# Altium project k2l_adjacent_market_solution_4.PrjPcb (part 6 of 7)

## Sheet system_power_01.SchDoc
size 431 x 279 mm; Date: Not shown in title block; ApprovedBy: Not shown in title block; CheckedBy: Not shown in title block; Author: Not shown in title block; CompanyName: Not shown in title block; DrawnBy: a0271760; Engineer: Not shown in title block; Organization: Not shown in title block; Address1: Not shown in title block; Address2: Not shown in title block; Address3: Not shown in title block; Address4: Not shown in title block; DocumentNumber: 34; Revision: Use project parameter SCH_Rev; SheetNumber: 34; SheetTotal: 38; PageSetup: Record=PageOptions¦CenterHorizontal=True¦CenterVertical=True¦PrintScale=0.64¦XCorrection=1.00¦YCorrection=1.00¦PrintKind=0¦BorderSize=5000000¦LeftOffset=0¦BottomOffset=0¦Orientation=2¦PaperLength=1000¦PaperWidth=1000¦Scale=100¦PaperSource=15¦PrintQuality=-3¦MediaType=1¦DitherType=10¦PrintScaleMode=1¦PaperKind=Letter¦PaperIndex=1
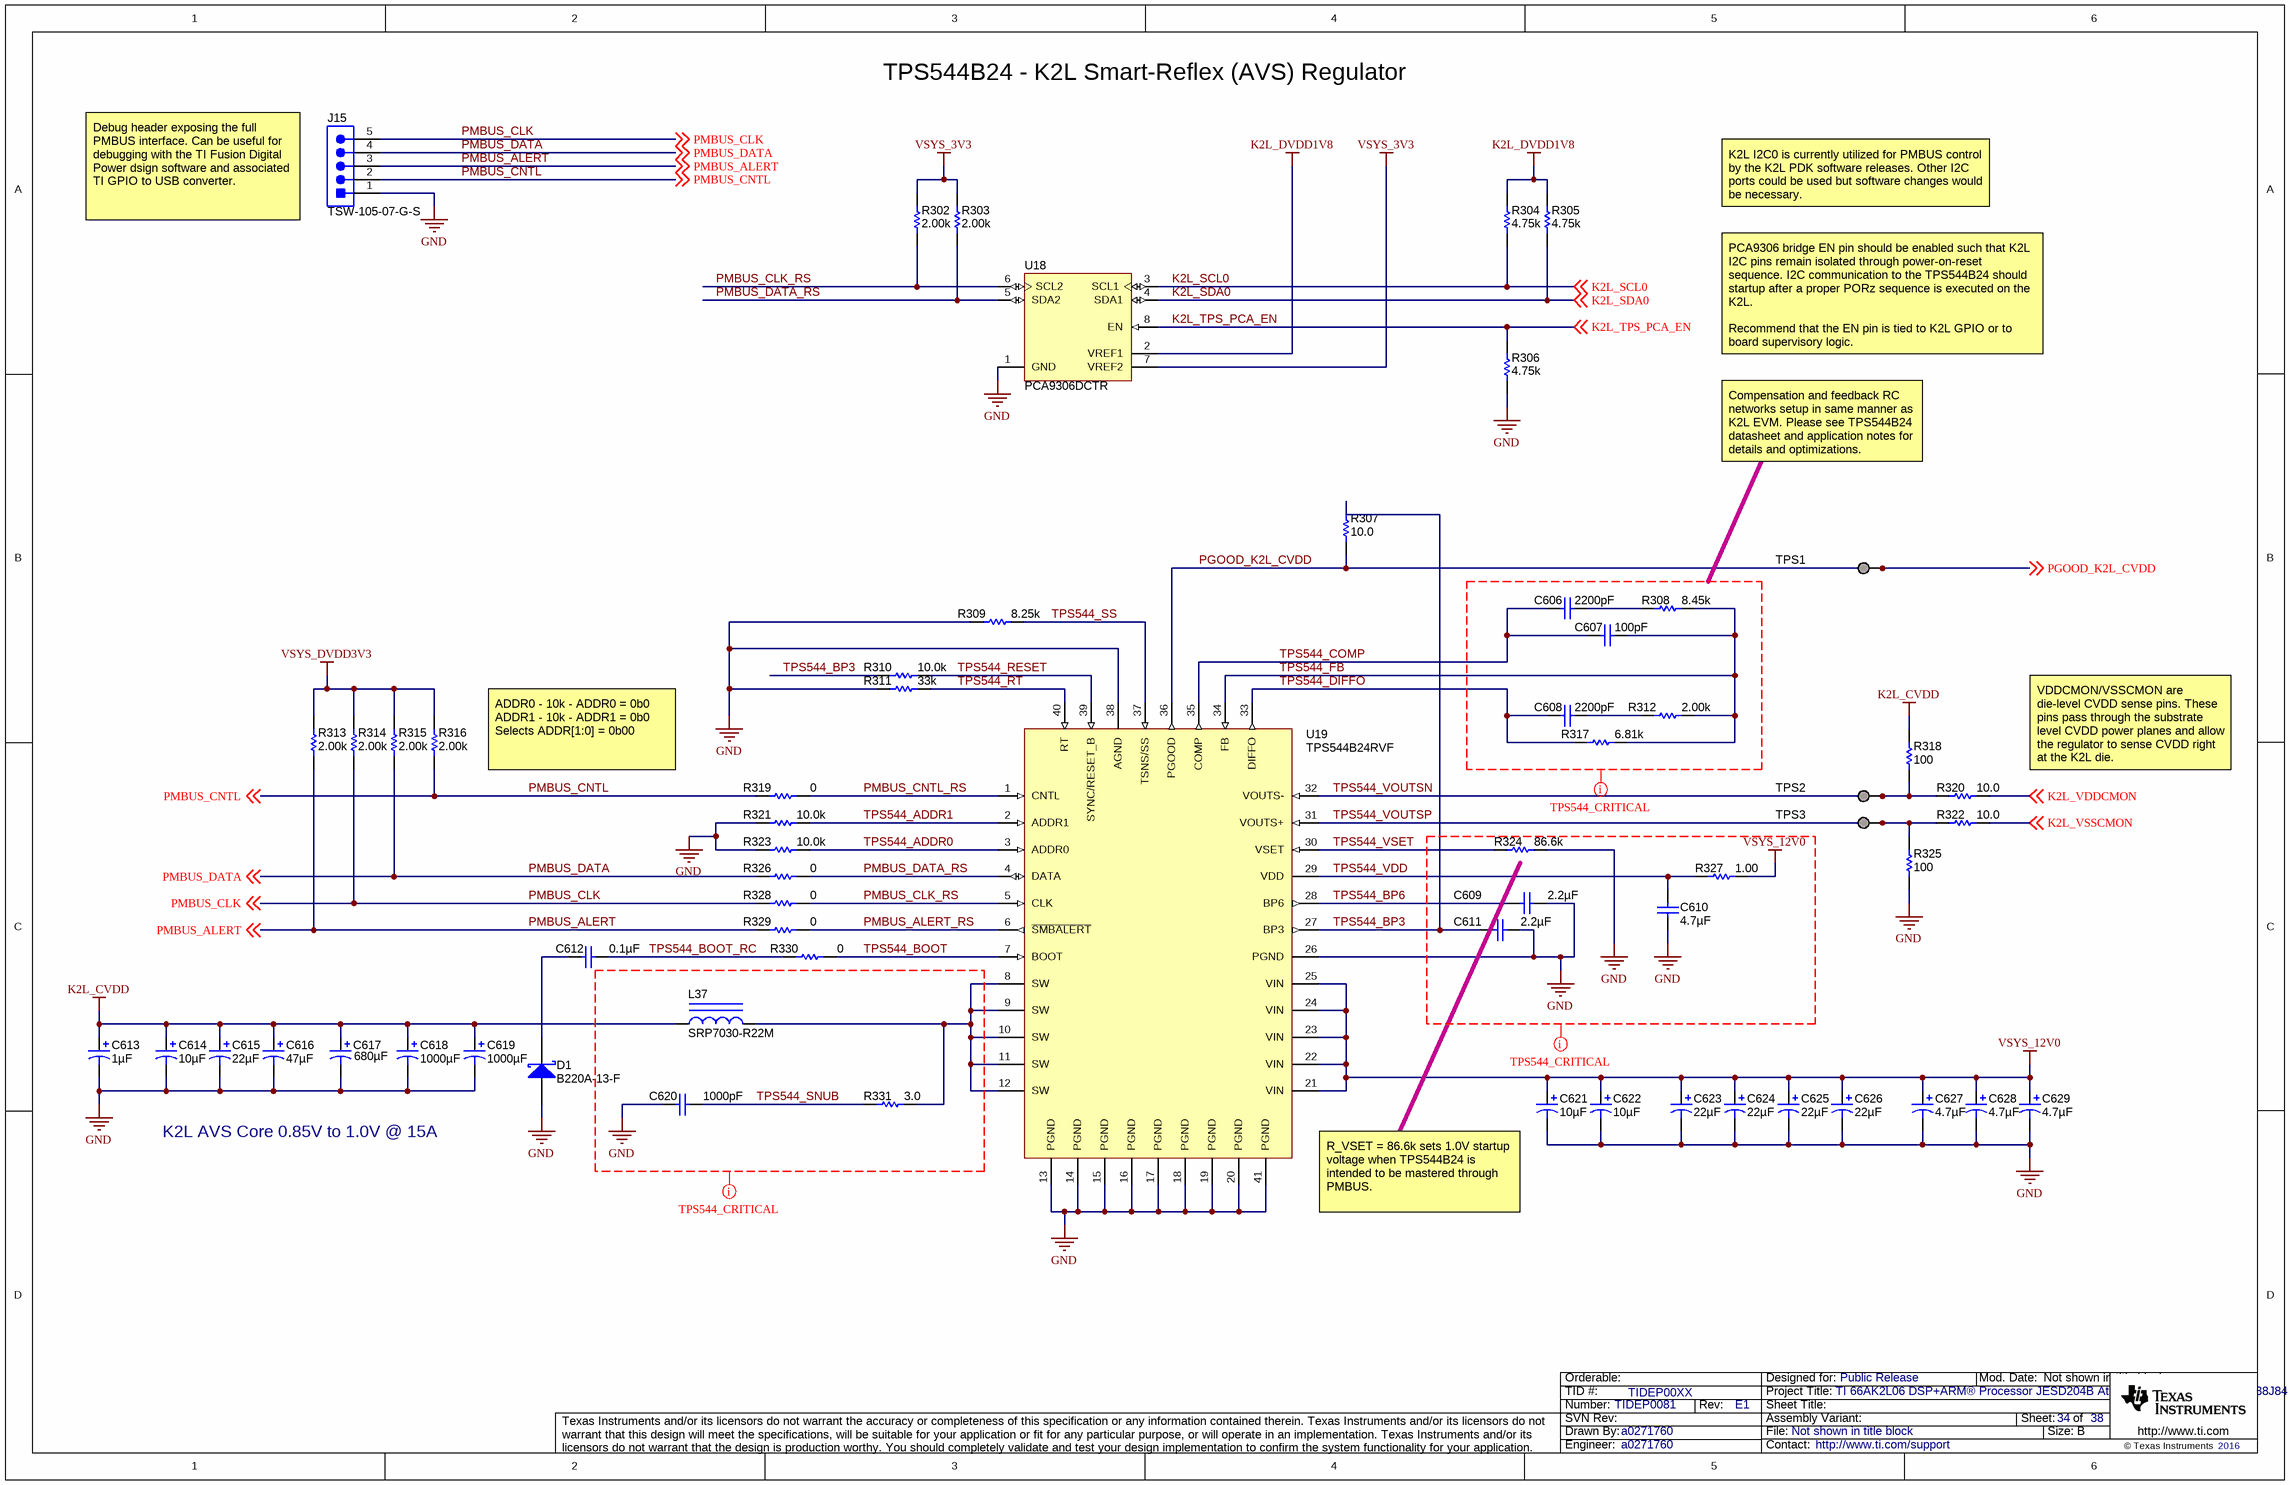
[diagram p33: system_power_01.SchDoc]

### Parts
C606  ValueDisplayed: 2200pF  [0402]  (hidden comment: C1005X7R1H222M)
C607  ValueDisplayed: 100pF  [0402]  (hidden comment: GRM1555C1H101JA01D)
C608  ValueDisplayed: 2200pF  [0402]  (hidden comment: C1005X7R1H222M)
C609  ValueDisplayed: 2.2µF  [0402]  (hidden comment: GRM155B31A225ME95)
C610  ValueDisplayed: 4.7µF  [0402]  (hidden comment: GRM155R61E475ME15)
C611  ValueDisplayed: 2.2µF  [0402]  (hidden comment: GRM155B31A225ME95)
C612  ValueDisplayed: 0.1µF  [0402]  (hidden comment: GCM155R7IC104KA55D)
C613  ValueDisplayed: 1µF  [3216-18]  (hidden comment: T495A105K020ZTE3K0)
C614  ValueDisplayed: 10µF  [3216-18]  (hidden comment: T495A106K010ATE1K8)
C615  ValueDisplayed: 22µF  [3216-18]  (hidden comment: T495A226M010ZTE1K2ZV17)
C616  ValueDisplayed: 47µF  [6032-28]  (hidden comment: T495C476K006ATE250)
C617  ValueDisplayed: 680µF  [7343-31]  (hidden comment: TPSD687K004R0045)
C618  ValueDisplayed: 1000µF  [7260-38]  (hidden comment: T495E108K004ATE050)
C619  ValueDisplayed: 1000µF  [7260-38]  (hidden comment: T495E108K004ATE050)
C620  ValueDisplayed: 1000pF  [0402]  (hidden comment: GRM155R60J102KA01D)
C621  ValueDisplayed: 10µF  [3216-18]  (hidden comment: T495A106K010ATE1K8)
C622  ValueDisplayed: 10µF  [3216-18]  (hidden comment: T495A106K010ATE1K8)
C623  ValueDisplayed: 22µF  [3216-18]  (hidden comment: T495A226M010ZTE1K2ZV17)
C624  ValueDisplayed: 22µF  [3216-18]  (hidden comment: T495A226M010ZTE1K2ZV17)
C625  ValueDisplayed: 22µF  [3216-18]  (hidden comment: T495A226M010ZTE1K2ZV17)
C626  ValueDisplayed: 22µF  [3216-18]  (hidden comment: T495A226M010ZTE1K2ZV17)
C627  ValueDisplayed: 4.7µF  [3216-18]  (hidden comment: T495A475K010ZTE1K4)
C628  ValueDisplayed: 4.7µF  [3216-18]  (hidden comment: T495A475K010ZTE1K4)
C629  ValueDisplayed: 4.7µF  [3216-18]  (hidden comment: T495A475K010ZTE1K4)
D1  B220A-13-F  [SMA]
J15  TSW-105-07-G-S  [TSW-105-07-G-S]
L37  SRP7030-R22M  [SRP7030]
R302  ValueDisplayed: 2.00k  [0402]  (hidden comment: CRCW04022K00FKED)
R303  ValueDisplayed: 2.00k  [0402]  (hidden comment: CRCW04022K00FKED)
R304  ValueDisplayed: 4.75k  [0402]  (hidden comment: CRCW04024K75FKED)
R305  ValueDisplayed: 4.75k  [0402]  (hidden comment: CRCW04024K75FKED)
R306  ValueDisplayed: 4.75k  [0402]  (hidden comment: CRCW04024K75FKED)
R307  ValueDisplayed: 10.0  [0402]  (hidden comment: CRCW040210R0FKED)
R308  ValueDisplayed: 8.45k  [0402]  (hidden comment: CRCW04028K45FKED)
R309  ValueDisplayed: 8.25k  [0402]  (hidden comment: CRCW04028K25FKED)
R310  ValueDisplayed: 10.0k  [0402]  (hidden comment: CRCW040210K0FKED)
R311  ValueDisplayed: 33k  [0402]  (hidden comment: CRCW040233K0JNED)
R312  ValueDisplayed: 2.00k  [0402]  (hidden comment: CRCW04022K00FKED)
R313  ValueDisplayed: 2.00k  [0402]  (hidden comment: CRCW04022K00FKED)
R314  ValueDisplayed: 2.00k  [0402]  (hidden comment: CRCW04022K00FKED)
R315  ValueDisplayed: 2.00k  [0402]  (hidden comment: CRCW04022K00FKED)
R316  ValueDisplayed: 2.00k  [0402]  (hidden comment: CRCW04022K00FKED)
R317  ValueDisplayed: 6.81k  [0402]  (hidden comment: CRCW04026K81FKED)
R318  ValueDisplayed: 100  [0402]  (hidden comment: ERJ-2RKF1000X)
R319  ValueDisplayed: 0  [0402]  (hidden comment: CRCW04020000Z0ED)
R320  ValueDisplayed: 10.0  [0402]  (hidden comment: CRCW040210R0FKED)
R321  ValueDisplayed: 10.0k  [0402]  (hidden comment: CRCW040210K0FKED)
R322  ValueDisplayed: 10.0  [0402]  (hidden comment: CRCW040210R0FKED)
R323  ValueDisplayed: 10.0k  [0402]  (hidden comment: CRCW040210K0FKED)
R324  ValueDisplayed: 86.6k  [0402]  (hidden comment: CRCW040286K6FKED)
R325  ValueDisplayed: 100  [0402]  (hidden comment: ERJ-2RKF1000X)
R326  ValueDisplayed: 0  [0402]  (hidden comment: CRCW04020000Z0ED)
R327  ValueDisplayed: 1.00  [1206]  (hidden comment: ERJ-8RQF1R0V)
R328  ValueDisplayed: 0  [0402]  (hidden comment: CRCW04020000Z0ED)
R329  ValueDisplayed: 0  [0402]  (hidden comment: CRCW04020000Z0ED)
R330  ValueDisplayed: 0  [0402]  (hidden comment: CRCW04020000Z0ED)
R331  ValueDisplayed: 3.0  [0402]  (hidden comment: CRCW04023R00JNED)
TPS1  TESTPOINT  [TESTPOINT]  (value not drawn)  (no BOM)
TPS2  TESTPOINT  [TESTPOINT]  (value not drawn)  (no BOM)
TPS3  TESTPOINT  [TESTPOINT]  (value not drawn)  (no BOM)
U18  PCA9306DCTR  [DCT0008A_N]
U19  TPS544B24RVF  [RVF0040A]

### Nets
GND: C609.1 C610.2 C611.1 C613.2(-) C614.2(-) C615.2(-) C616.2(-) C617.2(-) C618.2(-) C619.2(-) C620.2 C621.2(-) C622.2(-) C623.2(-) C624.2(-) C625.2(-) C626.2(-) C627.2(-) C628.2(-) C629.2(-) D1.2(A) J15.1 R306.1 R309.1 R311.2 R321.1 R323.1 R324.2 R325.1 U18.1(GND) U19.13(PGND) U19.14(PGND) U19.15(PGND) U19.16(PGND) U19.17(PGND) U19.18(PGND) U19.19(PGND) U19.20(PGND) U19.26(PGND) U19.38(AGND) U19.41(PGND)  [project net DAC_OUT0N_T1]
K2L_CVDD: C613.1(+) C614.1(+) C615.1(+) C616.1(+) C617.1(+) C618.1(+) C619.1(+) L37.1 R318.2
K2L_DVDD1V8: R304.2 R305.2 U18.2(VREF1)
VSYS_3V3: R302.2 R303.2 U18.7(VREF2)
VSYS_12V0: C621.1(+) C622.1(+) C623.1(+) C624.1(+) C625.1(+) C626.1(+) C627.1(+) C628.1(+) C629.1(+) R327.2 U19.21(VIN) U19.22(VIN) U19.23(VIN) U19.24(VIN) U19.25(VIN)
VSYS_DVDD3V3: R313.2 R314.2 R315.2 R316.2
K2L_SCL0: R304.1 U18.3(SCL1) ; off-sheet K2L_SCL0
K2L_SDA0: R305.1 U18.4(SDA1) ; off-sheet K2L_SDA0
K2L_TPS_PCA_EN: R306.2 U18.8(EN) ; off-sheet K2L_TPS_PCA_EN
K2L_VDDCMON: R320.2 ; off-sheet K2L_VDDCMON
K2L_VSSCMON: R322.2 ; off-sheet K2L_VSSCMON
PGOOD_K2L_CVDD: R307.2 TPS1.1 U19.36(PGOOD) ; off-sheet PGOOD_K2L_CVDD
PMBUS_ALERT: J15.3 R313.1 R329.1 ; off-sheet PMBUS_ALERT
PMBUS_ALERT_RS: R329.2 U19.6(~{SMBALERT})
PMBUS_CLK: J15.5 R314.1 R328.1 ; off-sheet PMBUS_CLK
PMBUS_CLK_RS: R302.1 R328.2 U18.6(SCL2) U19.5(CLK)
PMBUS_CNTL: J15.2 R316.1 R319.1 ; off-sheet PMBUS_CNTL
PMBUS_CNTL_RS: R319.2 U19.1(CNTL)
PMBUS_DATA: J15.4 R315.1 R326.1 ; off-sheet PMBUS_DATA
PMBUS_DATA_RS: R303.1 R326.2 U18.5(SDA2) U19.4(DATA)
TPS544_ADDR0: R323.2 U19.3(ADDR0)
TPS544_ADDR1: R321.2 U19.2(ADDR1)
TPS544_BOOT: R330.2 U19.7(BOOT)
TPS544_BOOT_RC: C612.1 R330.1
TPS544_BP3: C611.2 R307.1 R310.1 U19.27(BP3)
TPS544_BP6: C609.2 U19.28(BP6)
TPS544_COMP: C606.2 C607.1 U19.35(COMP)
TPS544_DIFFO: C608.2 R317.1 U19.33(DIFFO)
TPS544_FB: C607.2 R308.2 R312.2 R317.2 U19.34(FB)
TPS544_RESET: R310.2 U19.39(SYNC/RESET_B)
TPS544_RT: R311.1 U19.40(RT)
TPS544_SNUB: C620.1 R331.1
TPS544_SS: R309.2 U19.37(TSNS/SS)
TPS544_VDD: C610.1 R327.1 U19.29(VDD)
TPS544_VOUTSN: R318.1 R320.1 TPS2.1 U19.32(VOUTS-)
TPS544_VOUTSP: R322.1 R325.2 TPS3.1 U19.31(VOUTS+)
TPS544_VSET: R324.1 U19.30(VSET)
NetC606_1: C606.1 R308.1
NetC608_1: C608.1 R312.1
NetC612_2: C612.2 D1.1(K)
NetL37_2: L37.2 R331.2 U19.8(SW) U19.9(SW) U19.10(SW) U19.11(SW) U19.12(SW)

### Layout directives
net class Undefined: (no net found under the mark), GND, TPS544_SNUB, VSYS_12V0

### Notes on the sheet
- TPS544B24 - K2L Smart-Reflex (AVS) Regulator
- Debug header exposing the full PMBUS interface. Can be useful for debugging with the TI Fusion Digital Power dsign software and associated TI GPIO to USB converter.
- K2L I2C0 is currently utilized for PMBUS control by the K2L PDK software releases. Other I2C ports could be used but software changes would be necessary.
- PCA9306 bridge EN pin should be enabled such that K2L I2C pins remain isolated through power-on-reset sequence. I2C communication to the TPS544B24 should startup after a proper PORz sequence is executed on the K2L.
  Recommend that the EN pin is tied to K2L GPIO or to board supervisory logic.
- Compensation and feedback RC networks setup in same manner as K2L EVM. Please see TPS544B24 datasheet and application notes for details and optimizations.
- ADDR0 - 10k - ADDR0 = 0b0
  ADDR1 - 10k - ADDR1 = 0b0
  Selects ADDR[1:0] = 0b00
- VDDCMON/VSSCMON are die-level CVDD sense pins. These pins pass through the substrate level CVDD power planes and allow the regulator to sense CVDD right at the K2L die.
- K2L AVS Core 0.85V to 1.0V @ 15A
- R_VSET = 86.6k sets 1.0V startup voltage when TPS544B24 is intended to be mastered through PMBUS.

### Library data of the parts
C606 C608 = C1005X7R1H222M: CAP, CERM, 2200 pF, 50 V, +/- 20%, X7R, 0402; Manufacturer: TDK; Polarized: N; CompType: Capacitor; Value: 2200pF; U/M: EA; Cap_F: 0.0000000022; Tolerance_%: 20; ESR_ohm: 0.005; Value1: 0.005 ohm; VDC_V: 50; Value2: 50V; TaMin_C: -55; TaMax_C: 125
C607 = GRM1555C1H101JA01D: CAP, CERM, 100 pF, 50 V, +/- 5%, C0G/NP0, 0402; Manufacturer: MuRata; Polarized: N; CompType: Capacitor; Value: 100pF; U/M: EA; Cap_F: 0.0000000001; Tolerance_%: 5; Value1: Unknown; VDC_V: 50; Value2: 50V; TaMin_C: -55; TaMax_C: 125
C609 C611 = GRM155B31A225ME95: CAP, CERM, 2.2 µF, 10 V, +/- 20%, B, 0402; Manufacturer: MuRata; Polarized: N; CompType: Capacitor; Value: 2.2uF; U/M: EA; Cap_F: 0.0000022; Tolerance_%: 20; Value1: Unknown; VDC_V: 10; Value2: 10V; TaMin_C: -25; TaMax_C: 85
C610 = GRM155R61E475ME15: CAP, CERM, 4.7 µF, 25 V, +/- 20%, X5R, 0402; Manufacturer: MuRata; Polarized: N; CompType: Capacitor; Value: 4.7uF; U/M: EA; Cap_F: 0.0000047; Tolerance_%: 20; Value1: Unknown; VDC_V: 25; Value2: 25V; TaMin_C: -55; TaMax_C: 85
C612 = GCM155R7IC104KA55D: CAP, CERM, 0.1 µF, 16 V, +/- 10%, X7R, 0402; Manufacturer: MuRata; Polarized: N; CompType: Capacitor; Value: 0.1uF; U/M: EA; Cap_F: 0.0000001; Tolerance_%: 10; Value1: Unknown; VDC_V: 16; Value2: 16V; TaMin_C: -55; TaMax_C: 125
C613 = T495A105K020ZTE3K0: CAP, TA, 1 µF, 20 V, +/- 10%, 3 ohm, SMD; Manufacturer: Kemet; Polarized: Y; CompType: Capacitor; Value: 1uF; U/M: EA; Cap_F: 0.000001; Tolerance_%: 10; Value1: 3 ohm; VDC_V: 20; Value2: 20V; ESR_ohm: 3; IRMS_A: 0.142; TaMin_C: -55; TaMax_C: 125; Cap_Case: A
C614 C621 C622 = T495A106K010ATE1K8: CAP, TA, 10 µF, 10 V, +/- 10%, 1.8 ohm, SMD; Manufacturer: Kemet; Polarized: Y; CompType: Capacitor; Value: 10uF; U/M: EA; Cap_F: 0.00001; Tolerance_%: 10; Value1: 1.8 ohm; Value2: 10V; ESR_ohm: 1.8; TaMin_C: -55; TaMax_C: 125; Cap_Case: A
C615 C623-C626 = T495A226M010ZTE1K2ZV17: CAP, TA, 22 µF, 10 V, +/- 20%, 1.2 ohm, SMD; Manufacturer: Kemet; Polarized: Y; CompType: Capacitor; Value: 22uF; U/M: EA; Cap_F: 0.000022; Tolerance_%: 20; Value1: 1.2 ohm; VDC_V: 10; Value2: 10V; ESR_ohm: 1.2; TaMin_C: -55; TaMax_C: 125; Cap_Case: A
C616 = T495C476K006ATE250: CAP, TA, 47 µF, 6.3 V, +/- 10%, 0.25 ohm, SMD; Manufacturer: Kemet; Polarized: Y; CompType: Capacitor; Value: 47uF; U/M: EA; Cap_F: 0.000047; Tolerance_%: 10; VDC_V: 6.3; Value2: 6.3V; ESR_ohm: 0.25; IRMS_A: 0.597; TaMin_C: -55; TaMax_C: 125; Cap_Case: C
C617 = TPSD687K004R0045: CAP, TA, 680 µF, 4 V, +/- 10%, 0.045 ohm, SMD; Manufacturer: AVX; Polarized: Y; CompType: Capacitor; Value: 680uF; U/M: EA; Cap_F: 0.00068; Tolerance_%: 10; VDC_V: 4; Value2: 4V; ESR_ohm: 0.045; IRMS_A: 1.643; TaMin_C: -55; TaMax_C: 125; Cap_Case: D
C618 C619 = T495E108K004ATE050: CAP, TA, 1000 µF, 4 V, +/- 10%, 0.05 ohm, SMD; Manufacturer: Kemet; Polarized: Y; CompType: Capacitor; Value: 1000uF; U/M: EA; Cap_F: 0.001; Tolerance_%: 10; VDC_V: 4; Value2: 4V; ESR_ohm: 0.05; IRMS_A: 1.8; TaMin_C: -55; TaMax_C: 125; Cap_Case: E
C620 = GRM155R60J102KA01D: CAP, CERM, 1000 pF, 6.3 V, +/- 10%, X5R, 0402; Manufacturer: MuRata; Polarized: N; CompType: Capacitor; Value: 1000pF; U/M: EA; Cap_F: 0.000000001; Tolerance_%: 10; Value1: Unknown; VDC_V: 6.3; Value2: 6.3V; TaMin_C: -55; TaMax_C: 85
C627-C629 = T495A475K010ZTE1K4: CAP, TA, 4.7 µF, 10 V, +/- 10%, 1.4 ohm, SMD; Manufacturer: Kemet; Polarized: Y; CompType: Capacitor; Value: 4.7uF; U/M: EA; Cap_F: 0.0000047; Tolerance_%: 10; Value1: 1.4 ohm; Value2: 10V; ESR_ohm: 1.4; IRMS_A: 0.216; TaMin_C: -55; TaMax_C: 125; Cap_Case: A
D1 = B220A-13-F: Diode, Schottky, 20 V, 2 A, SMA; Manufacturer: Diodes Inc.; U/M: EA; Vf_V: 0.5; Value: 20V; Value1: 2A; Value2: 0.5V; Io_A: 2; Vr_V: 20; TJmax_C: 150
J15 = TSW-105-07-G-S: Header, 100mil, 5x1, Gold, TH; Manufacturer: Samtec; SymbolCreator: a0412235; U/M: EA
L37 = SRP7030-R22M: Inductor, Shielded, Powdered Iron, 220 nH, 23 A, 0.0028 ohm, SMD; Manufacturer: Bourns; Value: 220nH; Ind_H: 220.0E-9; Imax_A: 23; Irms: 23A @ 40C rise; Isat: 36A @ 20% inductance drop; DCR_ohm: 0.0028; Value2: 23A
R302 R303 R312-R316 = CRCW04022K00FKED: RES, 2.00 k, 1%, 0.063 W, 0402; Manufacturer: Vishay-Dale; CompType: Resistor; Value: 2.00k; Res_ohm: 2000; Value_Code: 2k00; Tolerance_%: 1; Power_W: 0.063; Value2: 0.063W; VDC_V: 50; TempCo: 100 ppm/C; EIA_Code: E96; U/M: EA
R304-R306 = CRCW04024K75FKED: RES, 4.75 k, 1%, 0.063 W, 0402; Manufacturer: Vishay-Dale; CompType: Resistor; Value: 4.75k; Res_ohm: 4750; Value_Code: 4k75; Tolerance_%: 1; Power_W: 0.063; Value2: 0.063W; VDC_V: 50; TempCo: 100 ppm/C; EIA_Code: E96; U/M: EA
R307 R320 R322 = CRCW040210R0FKED: RES, 10.0, 1%, 0.063 W, 0402; Manufacturer: Vishay-Dale; CompType: Resistor; Value: 10.0; Res_ohm: 10; Value_Code: 10R0; Tolerance_%: 1; Power_W: 0.063; Value2: 0.063W; VDC_V: 50; TempCo: 100 ppm/C; EIA_Code: E96; U/M: EA
R308 = CRCW04028K45FKED: RES, 8.45 k, 1%, 0.063 W, 0402; Manufacturer: Vishay-Dale; CompType: Resistor; Value: 8.45k; Res_ohm: 8450; Value_Code: 8k45; Tolerance_%: 1; Power_W: 0.063; Value2: 0.063W; VDC_V: 50; TempCo: 100 ppm/C; EIA_Code: E96; U/M: EA
R309 = CRCW04028K25FKED: RES, 8.25 k, 1%, 0.063 W, 0402; Manufacturer: Vishay-Dale; CompType: Resistor; Value: 8.25k; Res_ohm: 8250; Value_Code: 8k25; Tolerance_%: 1; Power_W: 0.063; Value2: 0.063W; VDC_V: 50; TempCo: 100 ppm/C; EIA_Code: E96; U/M: EA
R310 R321 R323 = CRCW040210K0FKED: RES, 10.0 k, 1%, 0.063 W, 0402; Manufacturer: Vishay-Dale; CompType: Resistor; Value: 10.0k; Res_ohm: 10000; Value_Code: 10k0; Tolerance_%: 1; Power_W: 0.063; Value2: 0.063W; VDC_V: 50; TempCo: 100 ppm/C; EIA_Code: E96; U/M: EA
R311 = CRCW040233K0JNED: RES, 33 k, 5%, 0.063 W, 0402; Manufacturer: Vishay-Dale; CompType: Resistor; Value: 33k; Res_ohm: 33000; Value_Code: 33k0; Tolerance_%: 5; Power_W: 0.063; Value2: 0.063W; VDC_V: 50; TempCo: 200 ppm/C; EIA_Code: E24; U/M: EA
R317 = CRCW04026K81FKED: RES, 6.81 k, 1%, 0.063 W, 0402; Manufacturer: Vishay-Dale; CompType: Resistor; Value: 6.81k; Res_ohm: 6810; Value_Code: 6k81; Tolerance_%: 1; Power_W: 0.063; Value2: 0.063W; VDC_V: 50; TempCo: 100 ppm/C; EIA_Code: E96; U/M: EA
R318 R325 = ERJ-2RKF1000X: RES, 100, 1%, 0.1 W, 0402; Manufacturer: Panasonic; CompType: Resistor; Value: 100; Value_Code: 100R; Tolerance_%: 1; Power_W: 0.1; Value2: 0.1W; VDC_V: 50; TempCo: 100 ppm/C; EIA_Code: E96; U/M: EA
R319 R326 R328-R330 = CRCW04020000Z0ED: RES, 0, 5%, 0.063 W, 0402; Manufacturer: Vishay-Dale; CompType: Resistor; Value: 0; Value_Code: 0000; Tolerance_%: 5; Power_W: 0.063; Value2: 0.063W; VDC_V: 50; TempCo: 200 ppm/C; EIA_Code: E24; U/M: EA
R324 = CRCW040286K6FKED: RES, 86.6 k, 1%, 0.063 W, 0402; Manufacturer: Vishay-Dale; CompType: Resistor; Value: 86.6k; Res_ohm: 86600; Value_Code: 86k6; Tolerance_%: 1; Power_W: 0.063; Value2: 0.063W; VDC_V: 50; TempCo: 100 ppm/C; EIA_Code: E96; U/M: EA
R327 = ERJ-8RQF1R0V: RES, 1.00, 1%, 0.25 W, 1206; Manufacturer: Panasonic; CompType: Resistor; Value: 1.00; Res_ohm: 1; Value_Code: 1R00; Power_W: 0.25; Value2: 0.25W; TempCo: 200 ppm/C; EIA_Code: E96; U/M: EA
R331 = CRCW04023R00JNED: RES, 3.0, 5%, 0.063 W, 0402; Manufacturer: Vishay-Dale; CompType: Resistor; Value: 3.0; Res_ohm: 3; Value_Code: 3R00; Tolerance_%: 5; Power_W: 0.063; Value2: 0.063W; VDC_V: 50; TempCo: 200 ppm/C; EIA_Code: E24; U/M: EA
TPS1-TPS3 = TESTPOINT: TEST POINT.  No entry in BOM.
U18 = PCA9306DCTR: Dual Bi-Directional I2C-Bus and SMBus Voltage Level-Translator, 0 to 5.5 V, -40 to 85 degC, 8-pin SM8 (DCT), Green (RoHS & no Sb/Br); Manufacturer: Texas Instruments; Alternate Manufacturer: None; Alternate PartNumber: Equivalent; SubFamily: I2C Special Function; No. of Outputs: 2; tpd max(ns): 1.5; fSCLK(Max)(MHz): 400; Function: Voltage Translator; Vcc range(V): 0 to 5.5; Enable Pin: Yes; Rating: Catalog
U19 = TPS544B24RVF: 18V, 20A PMBUS SYNCHRONOUS BUCK CONVERTERS, RVF0040A; Manufacturer: Texas Instruments; SymbolCreator: a0411947; CompType: IC; U/M: EA

## Sheet system_power_02.SchDoc
size 431 x 279 mm; Date: Not shown in title block; ApprovedBy: Not shown in title block; CheckedBy: Not shown in title block; Author: Not shown in title block; CompanyName: Not shown in title block; Engineer: Not shown in title block; Organization: Not shown in title block; Address1: Not shown in title block; Address2: Not shown in title block; Address3: Not shown in title block; Address4: Not shown in title block; DocumentNumber: 35; Revision: Use project parameter SCH_Rev; SheetNumber: 35; SheetTotal: 38; PageSetup: Record=PageOptions¦CenterHorizontal=True¦CenterVertical=True¦PrintScale=1.00¦XCorrection=1.00¦YCorrection=1.00¦PrintKind=0¦BorderSize=5000000¦LeftOffset=0¦BottomOffset=0¦Orientation=2¦PaperLength=1000¦PaperWidth=1000¦Scale=100¦PaperSource=15¦PrintQuality=600¦MediaType=1¦DitherType=10¦PaperKind=Letter¦PrintScaleMode=1
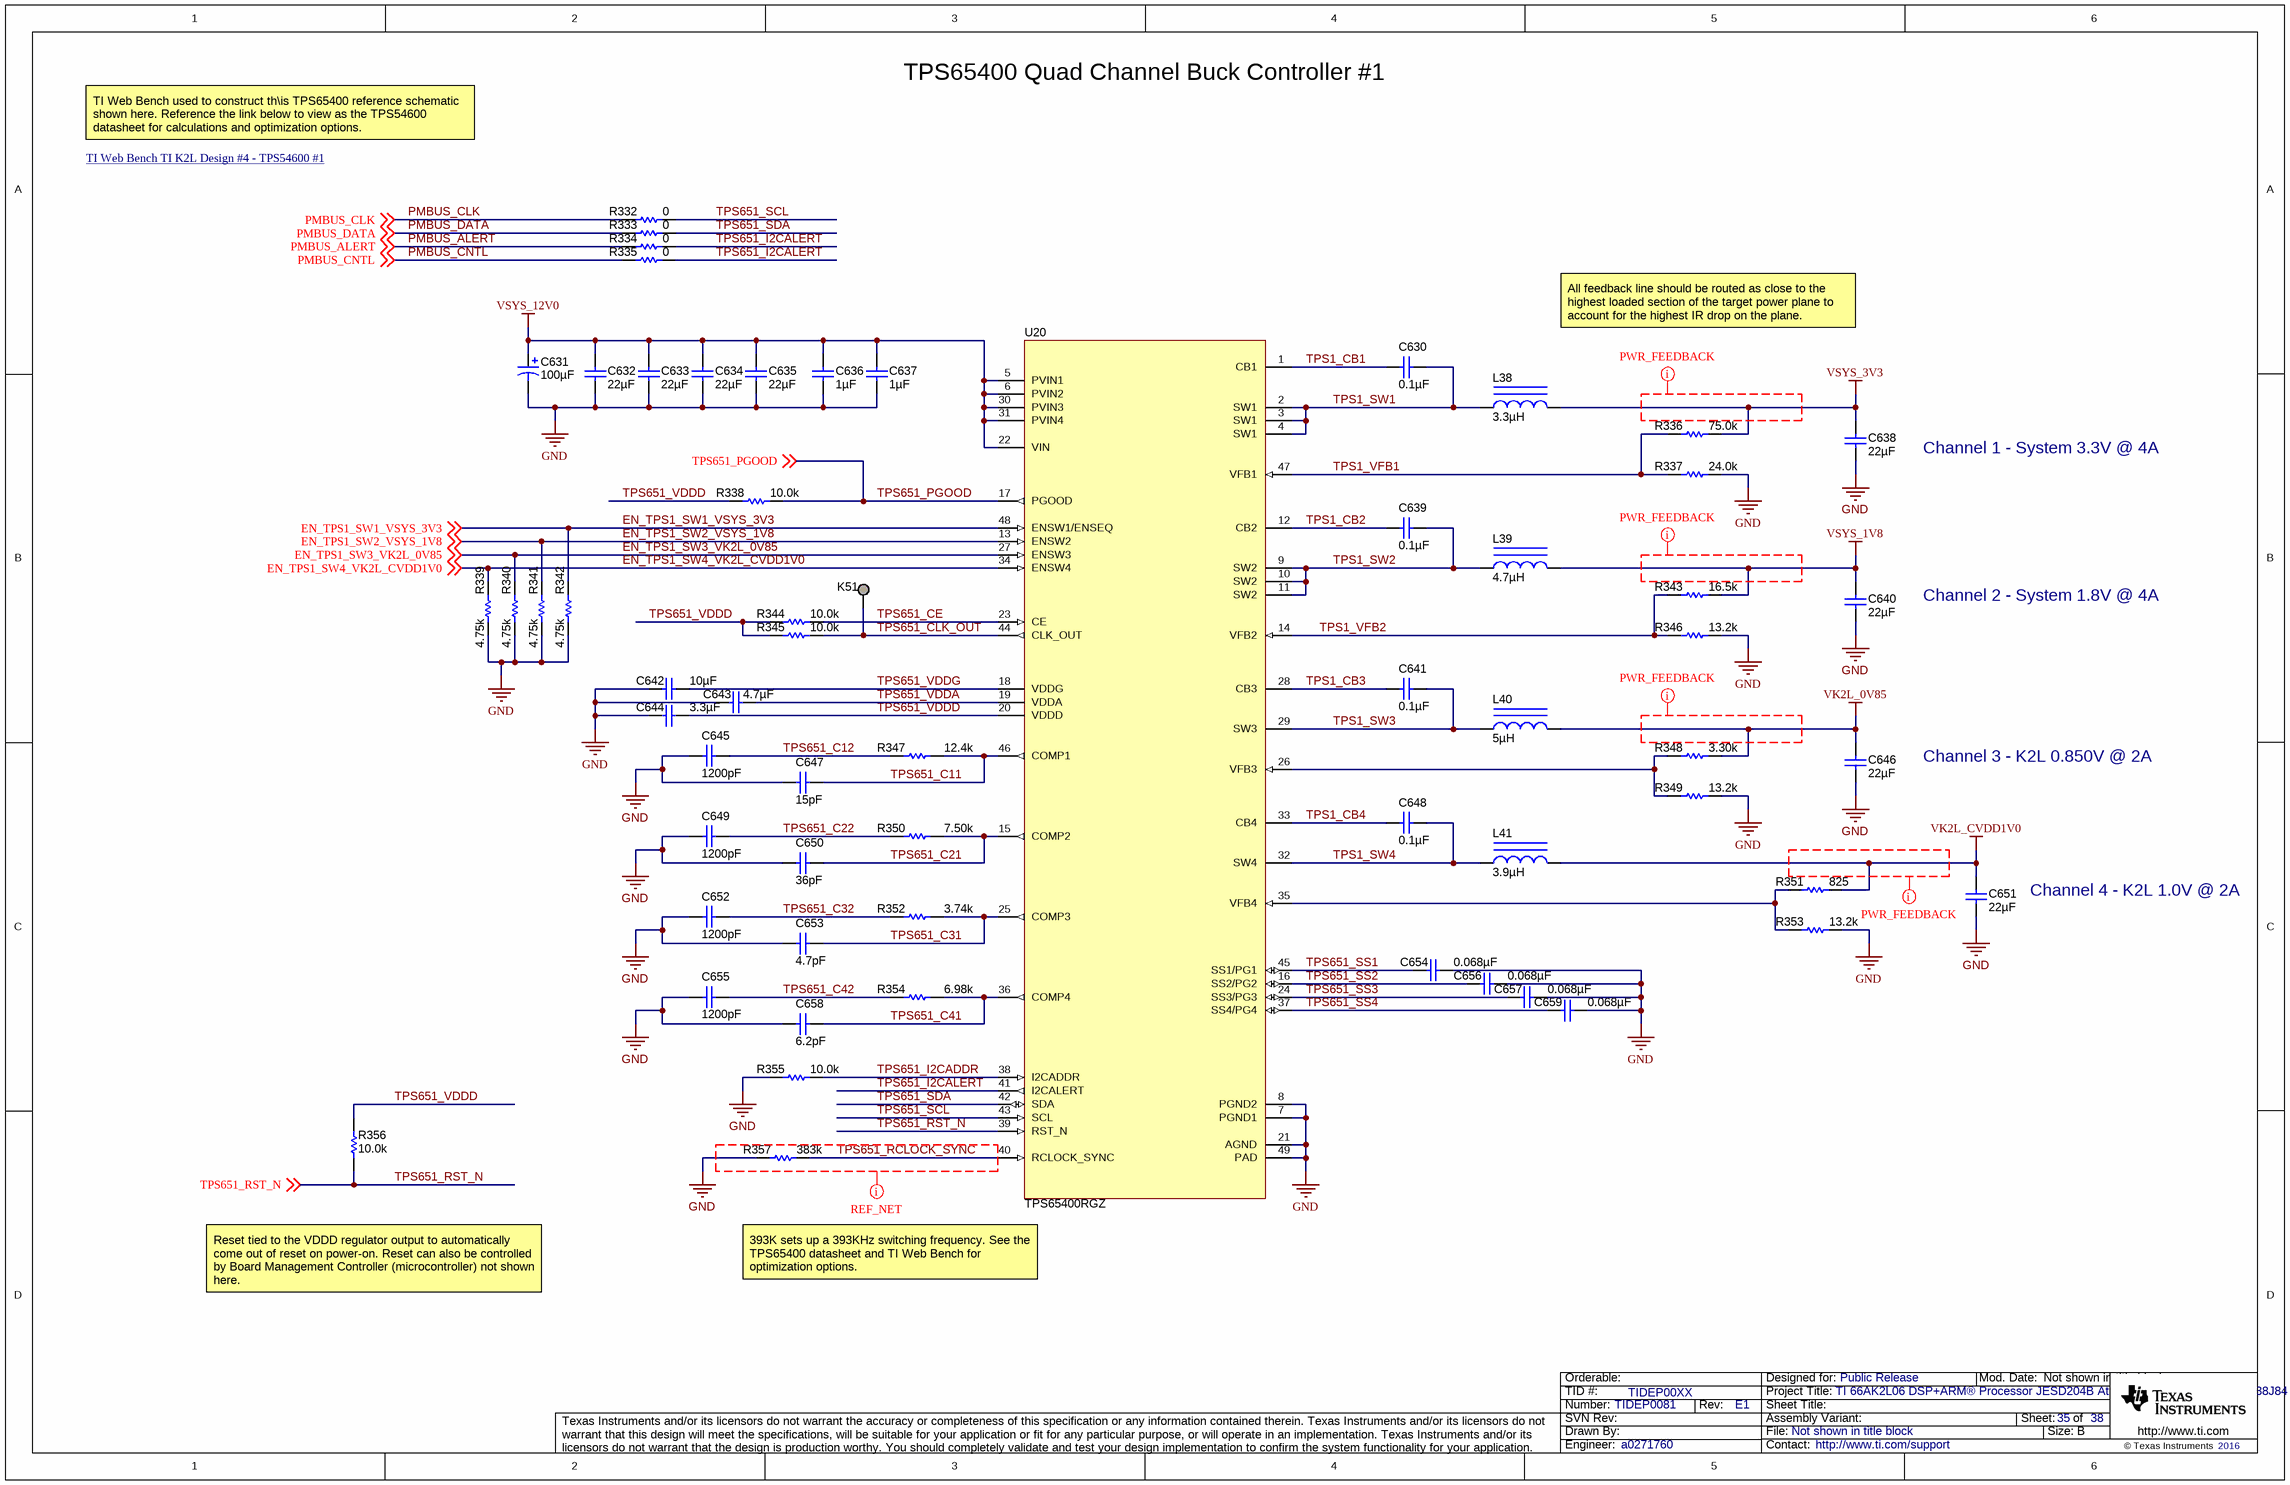
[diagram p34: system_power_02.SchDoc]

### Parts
C630  ValueDisplayed: 0.1µF  [0805_HV]  (hidden comment: 08053C104KAT2A)
C631  ValueDisplayed: 100µF  [6032-28]  (hidden comment: T495C107M006ATE150)
C632  ValueDisplayed: 22µF  [1210_270]  (hidden comment: GRM32ER61E226KE15L)
C633  ValueDisplayed: 22µF  [1210_270]  (hidden comment: GRM32ER61E226KE15L)
C634  ValueDisplayed: 22µF  [1210_270]  (hidden comment: GRM32ER61E226KE15L)
C635  ValueDisplayed: 22µF  [1210_270]  (hidden comment: GRM32ER61E226KE15L)
C636  ValueDisplayed: 1µF  [0603]  (hidden comment: GRM188R61E105KA12D)
C637  ValueDisplayed: 1µF  [0603]  (hidden comment: GRM188R61E105KA12D)
C638  ValueDisplayed: 22µF  [1210_270]  (hidden comment: GRM32ER61E226KE15L)
C639  ValueDisplayed: 0.1µF  [0805_HV]  (hidden comment: 08053C104KAT2A)
C640  ValueDisplayed: 22µF  [1210_270]  (hidden comment: GRM32ER61E226KE15L)
C641  ValueDisplayed: 0.1µF  [0805_HV]  (hidden comment: 08053C104KAT2A)
C642  ValueDisplayed: 10µF  [0603]  (hidden comment: GRM188R61E106MA73D)
C643  ValueDisplayed: 4.7µF  [0603]  (hidden comment: GRM188R61E475KE11D)
C644  ValueDisplayed: 3.3µF  [0603]  (hidden comment: GRM188R61A335KE15D)
C645  ValueDisplayed: 1200pF  [0402]  (hidden comment: GRM155R71H122KA01D)
C646  ValueDisplayed: 22µF  [1210_270]  (hidden comment: GRM32ER61E226KE15L)
C647  ValueDisplayed: 15pF  [0603]  (hidden comment: GCM1885C1H150JA16D)
C648  ValueDisplayed: 0.1µF  [0805_HV]  (hidden comment: 08053C104KAT2A)
C649  ValueDisplayed: 1200pF  [0402]  (hidden comment: GRM155R71H122KA01D)
C650  ValueDisplayed: 36pF  [0402]  (hidden comment: GRM1555C1E360JA01D)
C651  ValueDisplayed: 22µF  [1210_270]  (hidden comment: GRM32ER61E226KE15L)
C652  ValueDisplayed: 1200pF  [0402]  (hidden comment: GRM155R71H122KA01D)
C653  ValueDisplayed: 4.7pF  [0402]  (hidden comment: GRM1555C1H4R7WA01D)
C654  ValueDisplayed: 0.068µF  [0402]  (hidden comment: GRM155R61A683KA01D)
C655  ValueDisplayed: 1200pF  [0402]  (hidden comment: GRM155R71H122KA01D)
C656  ValueDisplayed: 0.068µF  [0402]  (hidden comment: GRM155R61A683KA01D)
C657  ValueDisplayed: 0.068µF  [0402]  (hidden comment: GRM155R61A683KA01D)
C658  ValueDisplayed: 6.2pF  [0402]  (hidden comment: GRM1555C1E6R2CA01D)
C659  ValueDisplayed: 0.068µF  [0402]  (hidden comment: GRM155R61A683KA01D)
K51  TESTPOINT  [TESTPOINT]  (value not drawn)  (no BOM)
L38  ValueDisplayed: 3.3µH  [IHLP-2020CZ]  (hidden comment: IHLP2020CZER3R3M11)
L39  ValueDisplayed: 4.7µH  [WE-HC4]  (hidden comment: 744311470)
L40  ValueDisplayed: 5µH  [SRR6038]  (hidden comment: SRR6038-5R0Y)
L41  ValueDisplayed: 3.9µH  [IHSM7832]  (hidden comment: IHSM7832ER3R9L)
R332  ValueDisplayed: 0  [0402]  (hidden comment: CRCW04020000Z0ED)
R333  ValueDisplayed: 0  [0402]  (hidden comment: CRCW04020000Z0ED)
R334  ValueDisplayed: 0  [0402]  (hidden comment: CRCW04020000Z0ED)
R335  ValueDisplayed: 0  [0402]  (hidden comment: CRCW04020000Z0ED)
R336  ValueDisplayed: 75.0k  [0402]  (hidden comment: CRCW040275K0FKED)
R337  ValueDisplayed: 24.0k  [0603]  (hidden comment: RC0603FR-0724KL)
R338  ValueDisplayed: 10.0k  [0402]  (hidden comment: CRCW040210K0FKED)
R339  ValueDisplayed: 4.75k  [0402]  (hidden comment: CRCW04024K75FKED)
R340  ValueDisplayed: 4.75k  [0402]  (hidden comment: CRCW04024K75FKED)
R341  ValueDisplayed: 4.75k  [0402]  (hidden comment: CRCW04024K75FKED)
R342  ValueDisplayed: 4.75k  [0402]  (hidden comment: CRCW04024K75FKED)
R343  ValueDisplayed: 16.5k  [0402]  (hidden comment: CRCW040216K5FKED)
R344  ValueDisplayed: 10.0k  [0402]  (hidden comment: CRCW040210K0FKED)
R345  ValueDisplayed: 10.0k  [0402]  (hidden comment: CRCW040210K0FKED)
R346  ValueDisplayed: 13.2k  [0805_HV]  (hidden comment: RT0805BRD0713K2L)
R347  ValueDisplayed: 12.4k  [0402]  (hidden comment: CRCW040212K4FKED)
R348  ValueDisplayed: 3.30k  [0603]  (hidden comment: RC0603FR-073K3L)
R349  ValueDisplayed: 13.2k  [0805_HV]  (hidden comment: RT0805BRD0713K2L)
R350  ValueDisplayed: 7.50k  [0402]  (hidden comment: CRCW04027K50FKED)
R351  ValueDisplayed: 825  [0402]  (hidden comment: CRCW0402825RFKED)
R352  ValueDisplayed: 3.74k  [0402]  (hidden comment: CRCW04023K74FKED)
R353  ValueDisplayed: 13.2k  [0805_HV]  (hidden comment: RT0805BRD0713K2L)
R354  ValueDisplayed: 6.98k  [0402]  (hidden comment: CRCW04026K98FKED)
R355  ValueDisplayed: 10.0k  [0402]  (hidden comment: CRCW040210K0FKED)
R356  ValueDisplayed: 10.0k  [0402]  (hidden comment: CRCW040210K0FKED)
R357  ValueDisplayed: 383k  [0402]  (hidden comment: CRCW0402383KFKED)
U20  TPS65400RGZ  [RGZ0048G]

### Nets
GND: C631.2(-) C632.2 C633.2 C634.2 C635.2 C636.2 C637.2 C638.2 C640.2 C642.2 C643.1 C644.1 C645.2 C646.2 C647.2 C649.2 C650.2 C651.2 C652.2 C653.2 C654.2 C655.2 C656.2 C657.2 C658.2 C659.2 R337.1 R339.1 R340.1 R341.1 R342.1 R346.2 R349.2 R353.2 R355.1 R357.1 U20.7(PGND1) U20.8(PGND2) U20.21(AGND) U20.49(PAD)  [project net DAC_OUT0N_T1]
VK2L_0V85: C646.1 L40.2 R348.2
VK2L_CVDD1V0: C651.1 L41.2 R351.2
VSYS_1V8: C640.1 L39.2 R343.2
VSYS_3V3: C638.1 L38.2 R336.1
VSYS_12V0: C631.1(+) C632.1 C633.1 C634.1 C635.1 C636.1 C637.1 U20.5(PVIN1) U20.6(PVIN2) U20.22(VIN) U20.30(PVIN3) U20.31(PVIN4)
EN_TPS1_SW1_VSYS_3V3: R342.2 U20.48(ENSW1/ENSEQ) ; off-sheet EN_TPS1_SW1_VSYS_3V3
EN_TPS1_SW2_VSYS_1V8: R341.2 U20.13(ENSW2) ; off-sheet EN_TPS1_SW2_VSYS_1V8
EN_TPS1_SW3_VK2L_0V85: R340.2 U20.27(ENSW3) ; off-sheet EN_TPS1_SW3_VK2L_0V85
EN_TPS1_SW4_VK2L_CVDD1V0: R339.2 U20.34(ENSW4) ; off-sheet EN_TPS1_SW4_VK2L_CVDD1V0
PMBUS_ALERT: R334.1 ; off-sheet PMBUS_ALERT
PMBUS_CLK: R332.1 ; off-sheet PMBUS_CLK
PMBUS_CNTL: R335.1 ; off-sheet PMBUS_CNTL
PMBUS_DATA: R333.1 ; off-sheet PMBUS_DATA
TPS1_CB1: C630.2 U20.1(CB1)
TPS1_CB2: C639.2 U20.12(CB2)
TPS1_CB3: C641.2 U20.28(CB3)
TPS1_CB4: C648.2 U20.33(CB4)
TPS1_SW1: C630.1 L38.1 U20.2(SW1) U20.3(SW1) U20.4(SW1)
TPS1_SW2: C639.1 L39.1 U20.9(SW2) U20.10(SW2) U20.11(SW2)
TPS1_SW3: C641.1 L40.1 U20.29(SW3)
TPS1_SW4: C648.1 L41.1 U20.32(SW4)
TPS1_VFB1: R336.2 R337.2 U20.47(VFB1)
TPS1_VFB2: R343.1 R346.1 U20.14(VFB2)
TPS651_C11: C647.1 R347.2 U20.46(COMP1)
TPS651_C12: C645.1 R347.1
TPS651_C21: C650.1 R350.2 U20.15(COMP2)
TPS651_C22: C649.1 R350.1
TPS651_C31: C653.1 R352.2 U20.25(COMP3)
TPS651_C32: C652.1 R352.1
TPS651_C41: C658.1 R354.2 U20.36(COMP4)
TPS651_C42: C655.1 R354.1
TPS651_CE: R344.2 U20.23(CE)
TPS651_CLK_OUT: K51.1 R345.2 U20.44(CLK_OUT)
TPS651_I2CADDR: R355.2 U20.38(I2CADDR)
TPS651_I2CALERT: R334.2 R335.2 U20.41(I2CALERT)
TPS651_PGOOD: R338.2 U20.17(PGOOD) ; off-sheet TPS651_PGOOD
TPS651_RCLOCK_SYNC: R357.2 U20.40(RCLOCK_SYNC)
TPS651_RST_N: R356.1 U20.39(RST_N) ; off-sheet TPS651_RST_N
TPS651_SCL: R332.2 U20.43(SCL)
TPS651_SDA: R333.2 U20.42(SDA)
TPS651_SS1: C654.1 U20.45(SS1/PG1)
TPS651_SS2: C656.1 U20.16(SS2/PG2)
TPS651_SS3: C657.1 U20.24(SS3/PG3)
TPS651_SS4: C659.1 U20.37(SS4/PG4)
TPS651_VDDA: C643.2 U20.19(VDDA)
TPS651_VDDD: C644.2 R338.1 R344.1 R345.1 R356.2 U20.20(VDDD)
TPS651_VDDG: C642.1 U20.18(VDDG)
NetR348_1: R348.1 R349.1 U20.26(VFB3)
NetR351_1: R351.1 R353.1 U20.35(VFB4)

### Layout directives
net class Undefined: (no net found under the mark), TPS651_RCLOCK_SYNC

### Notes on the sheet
- TPS65400 Quad Channel Buck Controller #1
- TI Web Bench used to construct th\is TPS65400 reference schematic shown here. Reference the link below to view as the TPS54600 datasheet for calculations and optimization options.
- TI Web Bench TI K2L Design #4 - TPS54600 #1 <https://webench.ti.com/wb5/OpenPublicSharedProject.jsp?id=32439A56866337B9&s=c>
- All feedback line should be routed as close to the highest loaded section of the target power plane to account for the highest IR drop on the plane.
- Channel 1 - System 3.3V @ 4A
- Channel 2 - System 1.8V @ 4A
- Channel 3 - K2L 0.850V @ 2A
- Channel 4 - K2L 1.0V @ 2A
- Reset tied to the VDDD regulator output to automatically come out of reset on power-on. Reset can also be controlled by Board Management Controller (microcontroller) not shown here.
- 393K sets up a 393KHz switching frequency. See the TPS65400 datasheet and TI Web Bench for optimization options.

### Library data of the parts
C630 C639 C641 C648 = 08053C104KAT2A: CAP, CERM, 0.1 µF, 25 V, +/- 10%, X7R, 0805; Manufacturer: AVX; Polarized: N; CompType: Capacitor; Value: 0.1uF; U/M: EA; Cap_F: 0.0000001; Tolerance_%: 10; ESR_ohm: 0.28; Value1: 0.28 ohm; VDC_V: 25; Value2: 25V; TaMin_C: -55; TaMax_C: 125; Cap_Case: 0805; SizeArea_mm2: 2.5; SizeAreaWB_mm2: 6.75; SizeX_mm: 2; SizeY_mm: 1.25; SizeZ_mm: 1.45; AEC Category: Q200
C631 = T495C107M006ATE150: CAP, TA, 100 µF, 6.3 V, +/- 20%, 0.15 ohm, SMD; Manufacturer: Kemet; Polarized: Y; CompType: Capacitor; Value: 100uF; U/M: EA; Cap_F: 0.0001; Tolerance_%: 20; VDC_V: 6.3; Value2: 6.3V; ESR_ohm: 0.15; IRMS_A: 0.77; TaMin_C: -55; TaMax_C: 125; Cap_Case: C; AEC Category: Q200
C632-C635 C638 C640 C646 C651 = GRM32ER61E226KE15L: CAP, CERM, 22 µF, 25 V, +/- 10%, X5R, 1210; Manufacturer: MuRata; Polarized: N; CompType: Capacitor; Value: 22uF; U/M: EA; Cap_F: 0.000022; Tolerance_%: 10; ESR_ohm: 0.002; Value1: 0.002 ohm; VDC_V: 25; Value2: 25V; IRMS_A: 3.67; TaMin_C: -55; TaMax_C: 85; Cap_Case: 1210; SizeArea_mm2: 8; SizeAreaWB_mm2: 14.7; SizeX_mm: 3.2; SizeY_mm: 2.5; SizeZ_mm: 2.7; AEC Category: Q200
C636 C637 = GRM188R61E105KA12D: CAP, CERM, 1 µF, 25 V, +/- 10%, X5R, 0603; Manufacturer: MuRata; Polarized: N; CompType: Capacitor; Value: 1uF; U/M: EA; Cap_F: 0.000001; Tolerance_%: 10; Value1: Unknown; VDC_V: 25; Value2: 25V; TaMin_C: -55; TaMax_C: 85; SizeArea_mm2: 1.28; SizeAreaWB_mm2: 4.68; SizeX_mm: 1.6; SizeY_mm: 0.8; SizeZ_mm: 1; AEC Category: Q200
C642 = GRM188R61E106MA73D: CAP, CERM, 10 µF, 25 V, +/- 20%, X5R, 0603; Manufacturer: MuRata; Polarized: N; CompType: Capacitor; Value: 10uF; U/M: EA; Cap_F: 0.00001; Tolerance_%: 20; Value1: Unknown; VDC_V: 25; Value2: 25V; TaMin_C: -55; TaMax_C: 85; SizeArea_mm2: 1.28; SizeAreaWB_mm2: 4.68; SizeX_mm: 1.6; SizeY_mm: 0.8; SizeZ_mm: 1; AEC Category: Q200
C643 = GRM188R61E475KE11D: CAP, CERM, 4.7 µF, 25 V, +/- 10%, X5R, 0603; Manufacturer: MuRata; Polarized: N; CompType: Capacitor; Value: 4.7uF; U/M: EA; Cap_F: 0.0000047; Tolerance_%: 10; Value1: Unknown; VDC_V: 25; Value2: 25V; TaMin_C: -55; TaMax_C: 85; SizeArea_mm2: 1.28; SizeAreaWB_mm2: 4.68; SizeX_mm: 1.6; SizeY_mm: 0.8; SizeZ_mm: 1; AEC Category: Q200
C644 = GRM188R61A335KE15D: CAP, CERM, 3.3 µF, 10 V, +/- 10%, X5R, 0603; Manufacturer: MuRata; Polarized: N; CompType: Capacitor; Value: 3.3uF; U/M: EA; Cap_F: 0.0000033; Tolerance_%: 10; ESR_ohm: 0.005; Value1: 0.005 ohm; Value2: 10V; IRMS_A: 1.7; TaMin_C: -55; TaMax_C: 85; SizeArea_mm2: 1.28; SizeAreaWB_mm2: 4.68; SizeX_mm: 1.6; SizeY_mm: 0.8; SizeZ_mm: 1; AEC Category: Q200
C645 C649 C652 C655 = GRM155R71H122KA01D: CAP, CERM, 1200 pF, 50 V, +/- 10%, X7R, 0402; Manufacturer: MuRata; Polarized: N; CompType: Capacitor; Value: 1200pF; U/M: EA; Cap_F: 0.0000000012; Tolerance_%: 10; Value1: Unknown; VDC_V: 50; Value2: 50V; TaMin_C: -55; TaMax_C: 125; SizeArea_mm2: 0.5; SizeAreaWB_mm2: 3; SizeX_mm: 1; SizeZ_mm: 0.6; AEC Category: Q200
C647 = GCM1885C1H150JA16D: CAP, CERM, 15 pF, 50 V, +/- 5%, C0G/NP0, AEC-Q200 Grade 1, 0603; Manufacturer: MuRata; Polarized: N; CompType: Capacitor; Value: 15pF; U/M: EA; Cap_F: 0.000000000015; Tolerance_%: 5; Value1: Unknown; VDC_V: 50; Value2: 50V; TaMin_C: -55; TaMax_C: 125; SizeArea_mm2: 1.28; SizeAreaWB_mm2: 4.68; SizeX_mm: 1.6; SizeY_mm: 0.8; SizeZ_mm: 1; AEC Category: Q200; AEC Qualified: Y
C650 = GRM1555C1E360JA01D: CAP, CERM, 36 pF, 25 V, +/- 5%, C0G/NP0, 0402; Manufacturer: MuRata; Polarized: N; CompType: Capacitor; Value: 36pF; U/M: EA; Cap_F: 0.000000000036; Tolerance_%: 5; Value1: Unknown; VDC_V: 25; Value2: 25V; TaMin_C: -55; TaMax_C: 125; SizeArea_mm2: 0.5; SizeAreaWB_mm2: 3; SizeX_mm: 1; SizeZ_mm: 0.6; AEC Category: Q200
C653 = GRM1555C1H4R7WA01D: CAP, CERM, 4.7 pF, 50 V, +/- 1%, C0G/NP0, 0402; Manufacturer: MuRata; Polarized: N; CompType: Capacitor; Value: 4.7pF; U/M: EA; Cap_F: 0.0000000000047; Tolerance_%: 1; Value1: Unknown; VDC_V: 50; Value2: 50V; TaMin_C: -55; TaMax_C: 125; SizeArea_mm2: 0.5; SizeAreaWB_mm2: 3; SizeZ_mm: 0.6; AEC Category: Q200
C654 C656 C657 C659 = GRM155R61A683KA01D: CAP, CERM, 0.068 µF, 10 V, +/- 10%, X5R, 0402; Manufacturer: MuRata; Polarized: N; CompType: Capacitor; Value: 0.068uF; U/M: EA; Cap_F: 0.000000068; Tolerance_%: 10; Value1: Unknown; Value2: 10V; TaMin_C: -55; TaMax_C: 85; SizeArea_mm2: 0.5; SizeAreaWB_mm2: 3; SizeX_mm: 1; SizeZ_mm: 0.6; AEC Category: Q200
C658 = GRM1555C1E6R2CA01D: CAP, CERM, 6.2 pF, 25 V, +/- 5%, C0G/NP0, 0402; Manufacturer: MuRata; Polarized: N; CompType: Capacitor; Value: 6.2pF; U/M: EA; Cap_F: 0.0000000000062; Tolerance_%: 5; Value1: Unknown; VDC_V: 25; Value2: 25V; TaMin_C: -55; TaMax_C: 125; SizeArea_mm2: 0.5; SizeAreaWB_mm2: 3; SizeX_mm: 1; SizeZ_mm: 0.6; AEC Category: Q200
K51 = TESTPOINT: TEST POINT.  No entry in BOM.
L38 = IHLP2020CZER3R3M11: Inductor, Shielded Drum Core, Powdered Iron, 3.3 µH, 5.5 A, 0.0404 ohm, SMD; Manufacturer: Vishay-Dale; Value: 3.3uH; Ind_H: 3.3E-6; Imax_A: 5.5; Irms: 5.5A @ 40C rise; Isat: 7A @ 20% inductance drop; DCR_ohm: 0.0404; Value2: 5.5A; AEC Category: Q200
L39 = 744311470: Inductor, Shielded Drum Core, Superflux, 4.7 µH, 6 A, 0.02 ohm, SMD; Manufacturer: Wurth Elektronik; Value: 4.7uH; Ind_H: 4.7E-6; Imax_A: 6; Irms: 6A @ 50C rise; Isat: 7A @ 30% inductance drop; DCR_ohm: 0.02; Value2: 6A; AEC Category: Q200
L40 = SRR6038-5R0Y: Inductor, Drum Core, Ferrite, 5 µH, 2.9 A, 0.024 ohm, SMD; Manufacturer: Bourns; Value: 5uH; Ind_H: 5.0E-6; Imax_A: 2.9; Irms: 2.9A @ 30C rise; Isat: 2.95A @ 35% inductance drop; DCR_ohm: 0.024; Value2: 2.9A; AEC Category: Q200
L41 = IHSM7832ER3R9L: Inductor, Shielded Drum Core, Ferrite, 3.9 µH, 2.6 A, 0.02 ohm, SMD; Manufacturer: Vishay-Dale; Value: 3.9uH; Ind_H: 3.9E-6; Imax_A: 2.6; Irms: 7.3A @ 40C rise; Isat: 2.6A @ 5% inductance drop; DCR_ohm: 0.02; Value2: 2.6A; AEC Category: Q200
R332-R335 = CRCW04020000Z0ED: RES, 0, 5%, 0.063 W, 0402; Manufacturer: Vishay-Dale; CompType: Resistor; Value: 0; Value_Code: 0000; Tolerance_%: 5; Power_W: 0.063; Value2: 0.063W; VDC_V: 50; TempCo: 200 ppm/C; SizeArea_mm2: 0.5; SizeX_mm: 1; SizeZ_mm: 0.6; EIA_Code: E24; U/M: EA; AEC Category: Q200
R336 = CRCW040275K0FKED: RES, 75.0 k, 1%, 0.063 W, 0402; Manufacturer: Vishay-Dale; CompType: Resistor; Value: 75.0k; Res_ohm: 75000; Value_Code: 75k0; Tolerance_%: 1; Power_W: 0.063; Value2: 0.063W; VDC_V: 50; TempCo: 100 ppm/C; SizeArea_mm2: 0.5; SizeZ_mm: 0.6; EIA_Code: E96; U/M: EA; AEC Category: Q200
R337 = RC0603FR-0724KL: RES, 24.0 k, 1%, 0.1 W, 0603; Manufacturer: Yageo America; CompType: Resistor; Value: 24.0k; Res_ohm: 24000; Value_Code: 24k0; Tolerance_%: 1; Power_W: 0.1; Value2: 0.1W; VDC_V: 150; TempCo: 200 ppm/C; SizeArea_mm2: 1.28; SizeX_mm: 1.6; SizeY_mm: 0.8; U/M: EA; AEC Category: Q200
R338 R344 R345 R355 R356 = CRCW040210K0FKED: as R310 on sheet system_power_01
R339-R342 = CRCW04024K75FKED: as R304-R306 on sheet system_power_01
R343 = CRCW040216K5FKED: RES, 16.5 k, 1%, 0.063 W, 0402; Manufacturer: Vishay-Dale; CompType: Resistor; Value: 16.5k; Res_ohm: 16500; Value_Code: 16k5; Tolerance_%: 1; Power_W: 0.063; Value2: 0.063W; VDC_V: 50; TempCo: 100 ppm/C; SizeArea_mm2: 0.5; SizeZ_mm: 0.6; EIA_Code: E96; U/M: EA; AEC Category: Q200
R346 R349 R353 = RT0805BRD0713K2L: RES, 13.2 k, 0.1%, 0.125 W, 0805; Manufacturer: Yageo America; CompType: Resistor; Value: 13.2k; Res_ohm: 13200; Value_Code: 13k2; Tolerance_%: 0.1; Power_W: 0.125; Value2: 0.125W; VDC_V: 150; TempCo: 25 ppm/C; SizeArea_mm2: 2.5; SizeX_mm: 2; SizeY_mm: 1.25; SizeZ_mm: 1.45; EIA_Code: E192; U/M: EA; AEC Category: Q200
R347 = CRCW040212K4FKED: RES, 12.4 k, 1%, 0.063 W, 0402; Manufacturer: Vishay-Dale; CompType: Resistor; Value: 12.4k; Res_ohm: 12400; Value_Code: 12k4; Tolerance_%: 1; Power_W: 0.063; Value2: 0.063W; VDC_V: 50; TempCo: 100 ppm/C; SizeArea_mm2: 0.5; SizeZ_mm: 0.6; EIA_Code: E96; U/M: EA; AEC Category: Q200
R348 = RC0603FR-073K3L: RES, 3.30 k, 1%, 0.1 W, 0603; Manufacturer: Yageo America; CompType: Resistor; Value: 3.30k; Res_ohm: 3300; Value_Code: 3k30; Tolerance_%: 1; Power_W: 0.1; Value2: 0.1W; VDC_V: 150; TempCo: 200 ppm/C; SizeArea_mm2: 1.28; SizeX_mm: 1.6; SizeY_mm: 0.8; U/M: EA; AEC Category: Q200
R350 = CRCW04027K50FKED: RES, 7.50 k, 1%, 0.063 W, 0402; Manufacturer: Vishay-Dale; CompType: Resistor; Value: 7.50k; Res_ohm: 7500; Value_Code: 7k50; Tolerance_%: 1; Power_W: 0.063; Value2: 0.063W; VDC_V: 50; TempCo: 100 ppm/C; SizeArea_mm2: 0.5; SizeZ_mm: 0.6; EIA_Code: E96; U/M: EA; AEC Category: Q200
R351 = CRCW0402825RFKED: RES, 825, 1%, 0.063 W, 0402; Manufacturer: Vishay-Dale; CompType: Resistor; Value: 825; Value_Code: 825R; Tolerance_%: 1; Power_W: 0.063; Value2: 0.063W; VDC_V: 50; TempCo: 100 ppm/C; SizeArea_mm2: 0.5; SizeZ_mm: 0.6; EIA_Code: E96; U/M: EA; AEC Category: Q200
R352 = CRCW04023K74FKED: RES, 3.74 k, 1%, 0.063 W, 0402; Manufacturer: Vishay-Dale; CompType: Resistor; Value: 3.74k; Res_ohm: 3740; Value_Code: 3k74; Tolerance_%: 1; Power_W: 0.063; Value2: 0.063W; VDC_V: 50; TempCo: 100 ppm/C; SizeArea_mm2: 0.5; SizeZ_mm: 0.6; EIA_Code: E96; U/M: EA; AEC Category: Q200
R354 = CRCW04026K98FKED: RES, 6.98 k, 1%, 0.063 W, 0402; Manufacturer: Vishay-Dale; CompType: Resistor; Value: 6.98k; Res_ohm: 6980; Value_Code: 6k98; Tolerance_%: 1; Power_W: 0.063; Value2: 0.063W; VDC_V: 50; TempCo: 100 ppm/C; SizeArea_mm2: 0.5; SizeZ_mm: 0.6; EIA_Code: E96; U/M: EA; AEC Category: Q200
R357 = CRCW0402383KFKED: RES, 383 k, 1%, 0.063 W, 0402; Manufacturer: Vishay-Dale; CompType: Resistor; Value: 383k; Res_ohm: 383000; Tolerance_%: 1; Power_W: 0.063; Value2: 0.063W; VDC_V: 50; TempCo: 100 ppm/C; SizeArea_mm2: 0.5; SizeZ_mm: 0.6; EIA_Code: E96; U/M: EA; AEC Category: Q200
U20 = TPS65400RGZ: 4.5V TO 18V INPUT FLEXIBLE POWER MANAGEMENT UNIT WITH PMBus/ I2C AND INTEGRATED SEQUENCING, RGZ0048G; Manufacturer: Texas Instruments; SymbolCreator: a0411947; CompType: IC; U/M: EA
